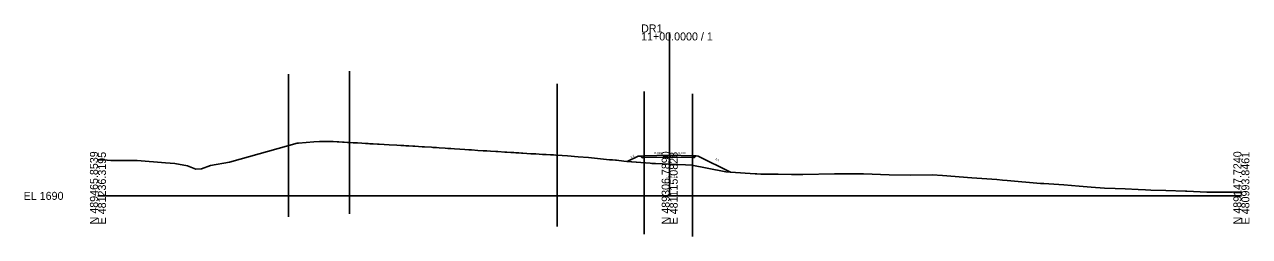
# Model space of a CAD drawing. Extents: x -26 to 403, y -28 to 1060.
# Drawn here: x -25.7 to 402.8, y 985.7 to 1060.1 of the extents above; entities that cross this region are included whole.
import ezdxf

# ---------------------------------------------------------------- set-up
doc = ezdxf.new("R2010")
doc.units = 0
for name, color, linetype in [('Exist Cross Section Cell', 7, 'Continuous'), ('Exist XS Center Line Elevation Label', 7, 'Continuous'), ('Exist XS Ground Line', 7, 'Continuous'), ('Prop XS Dump Level', 7, 'Continuous'), ('Prop XS Earthwork Shape', 7, 'Continuous'), ('Prop XS EOT Tick Mark', 7, 'Continuous'), ('Prop XS Finish Grade', 7, 'Continuous'), ('Prop XS Finish Grade Earthwork', 7, 'Continuous'), ('Prop XS Finish Grade Pavement', 7, 'Continuous'), ('Prop XS Pvmt Edge Slope', 7, 'Continuous'), ('Prop XS SE Text', 7, 'Continuous'), ('Prop XS Shoulder Borrow Shape', 7, 'Continuous'), ('Prop XS Side Slope Text', 7, 'Continuous'), ('Prop XS Subgrade Earthwork', 7, 'Continuous'), ('Scratch_Level_4', 7, 'Continuous'), ('Scratch_Level_5', 7, 'Continuous')]:
    doc.layers.add(name, color=color, linetype=linetype)

msp = doc.modelspace()

# ---------------------------------------------------------------- linework, layer by layer
at = {"layer": 'Exist Cross Section Cell'}
for p, q in [((200, 1000), (200, 1057.27)), ((0, 1000), (200, 1000)), ((200, 1000), (400, 1000))]:
    msp.add_line(p, q, dxfattribs=at)
at = {"layer": 'Exist XS Ground Line'}
msp.add_lwpolyline([(0, 1012.58), (1.9, 1012.57), (4.51, 1012.41), (13.68, 1012.41), (23.65, 1011.61), (26.89, 1011.39), (31.29, 1010.48), (34.2, 1009.4), (36.24, 1009.52), (39.35, 1010.61), (45.99, 1011.81), (69.73, 1018.47), (70.11, 1018.5), (75.53, 1018.99), (77.5, 1019.02), (77.95, 1019.04), (80.71, 1019.08), (81.19, 1019.09), (82.26, 1019.03), (83.66, 1018.95), (84.25, 1018.91), (85.54, 1018.85), (86.14, 1018.81), (87.35, 1018.74), (88.27, 1018.69), (89.29, 1018.63), (89.8, 1018.6), (90.81, 1018.54), (92.36, 1018.45), (93.61, 1018.38), (94.49, 1018.32), (95.17, 1018.29), (96.29, 1018.22), (97.75, 1018.14), (98.32, 1018.11), (100.1, 1018.01), (101.9, 1017.91), (104.6, 1017.75), (106.01, 1017.66), (106.98, 1017.61), (107.73, 1017.56), (108.76, 1017.5), (110.1, 1017.42), (110.55, 1017.39), (110.89, 1017.37), (113.4, 1017.22), (114.2, 1017.17), (116.65, 1017.02), (117.16, 1016.99), (117.69, 1016.96), (118.39, 1016.92), (119.31, 1016.87), (121.41, 1016.72), (122.43, 1016.65), (123.03, 1016.61), (123.46, 1016.58), (124.78, 1016.49), (126.61, 1016.37), (128.36, 1016.25), (129.75, 1016.15), (130.16, 1016.13), (130.71, 1016.09), (132.88, 1015.95), (134.77, 1015.83), (135.49, 1015.79), (136.04, 1015.75), (137.29, 1015.67), (139.17, 1015.55), (139.86, 1015.5), (142.33, 1015.34), (143.02, 1015.3), (144.43, 1015.21), (145.47, 1015.15), (146.22, 1015.1), (147.2, 1015.04), (148.15, 1014.98), (148.61, 1014.95), (151.43, 1014.78), (152.15, 1014.74), (153.19, 1014.68), (154.37, 1014.61), (155.53, 1014.54), (156.75, 1014.47), (158.33, 1014.39), (159.33, 1014.33), (160.17, 1014.28), (162.37, 1014.17), (164.25, 1014.01), (167.95, 1013.72), (171.56, 1013.43), (178.9, 1012.67), (180.02, 1012.57), (181.06, 1012.49), (181.4, 1012.46), (183.96, 1012.12), (185.01, 1012.01), (193.23, 1011.44), (193.78, 1011.39), (194.08, 1011.39), (194.72, 1011.36), (195.02, 1011.35), (200, 1011.11), (205.57, 1010.85), (207.76, 1010.79), (213.14, 1009.67), (219.65, 1008.43), (221.26, 1008.28), (229.86, 1007.77), (230.49, 1007.71), (231.92, 1007.65), (237.99, 1007.59), (242.62, 1007.44), (246.64, 1007.43), (257.7, 1007.68), (264.92, 1007.73), (266.54, 1007.76), (267.77, 1007.76), (276.75, 1007.37), (284.2, 1007.28), (291.78, 1007.35), (295.41, 1007.13), (305.75, 1006.29), (314.42, 1005.71), (316.49, 1005.54), (318.07, 1005.43), (329.78, 1004.38), (330.92, 1004.28), (337.9, 1003.82), (343.22, 1003.38), (347.42, 1003.02), (352.17, 1002.65), (355.8, 1002.53), (359.31, 1002.45), (363.92, 1002.21), (366.45, 1002.07), (368.37, 1002.01), (373.58, 1001.89), (380.42, 1001.67), (380.95, 1001.64), (387.86, 1001.34), (393.53, 1001.31), (394.99, 1001.33), (396.92, 1001.35), (400, 1001.38)], dxfattribs=at)
at = {"layer": 'Prop XS Dump Level'}
for p, q in [((191.12, 1014.06), (200, 1014.23)), ((200, 1014.23), (208, 1014.07))]:
    msp.add_line(p, q, dxfattribs=at)
at = {"layer": 'Prop XS Earthwork Shape'}
msp.add_lwpolyline([(189.74, 1013.96), (188.93, 1013.9), (185.15, 1012), (193.23, 1011.44), (193.78, 1011.39), (194.08, 1011.39), (194.72, 1011.36), (195.02, 1011.35), (200, 1011.11), (205.57, 1010.85), (207.76, 1010.79), (213.14, 1009.67), (219.65, 1008.43), (221.26, 1008.28), (210, 1013.91), (209.26, 1013.97), (208.68, 1013.39), (208, 1013.41), (200, 1013.57), (191.12, 1013.39), (190.38, 1013.38)], close=True, dxfattribs=at)
at = {"layer": 'Prop XS EOT Tick Mark'}
for p, q in [((191.12, 1014.06), (191.12, 1015.06)), ((208, 1014.07), (208, 1015.07))]:
    msp.add_line(p, q, dxfattribs=at)
at = {"layer": 'Prop XS Finish Grade'}
for p, q in [((191.12, 1014.06), (189.74, 1013.96)), ((208, 1014.07), (209.26, 1013.97))]:
    msp.add_line(p, q, dxfattribs=at)
at = {"layer": 'Prop XS Finish Grade Earthwork'}
for p, q in [((188.93, 1013.9), (185.15, 1012)), ((189.74, 1013.96), (188.93, 1013.9)), ((209.26, 1013.97), (210, 1013.91)), ((210, 1013.91), (221.26, 1008.28))]:
    msp.add_line(p, q, dxfattribs=at)
at = {"layer": 'Prop XS Finish Grade Pavement'}
for p, q in [((191.12, 1014.06), (200, 1014.23)), ((200, 1014.23), (208, 1014.07))]:
    msp.add_line(p, q, dxfattribs=at)
at = {"layer": 'Prop XS Pvmt Edge Slope'}
for p, q in [((191.12, 1014.06), (190.38, 1013.38)), ((208, 1014.07), (208.68, 1013.39))]:
    msp.add_line(p, q, dxfattribs=at)
at = {"layer": 'Prop XS Shoulder Borrow Shape'}
for points in [[(191.12, 1014.06), (190.38, 1013.38), (189.74, 1013.96)], [(208.68, 1013.39), (209.26, 1013.97), (208, 1014.07)]]:
    msp.add_lwpolyline(points, close=True, dxfattribs=at)
at = {"layer": 'Prop XS Subgrade Earthwork'}
for p, q in [((190.38, 1013.38), (189.74, 1013.96)), ((191.12, 1013.39), (190.38, 1013.38)), ((200, 1013.57), (191.12, 1013.39)), ((208, 1013.41), (200, 1013.57)), ((208, 1013.41), (208.68, 1013.39)), ((208.68, 1013.39), (209.26, 1013.97))]:
    msp.add_line(p, q, dxfattribs=at)
at = {"layer": 'Scratch_Level_4'}
for p, q in [((66.64, 1042.6), (66.64, 992.6)), ((87.99, 1043.7), (87.99, 993.7)), ((160.61, 1039.26), (160.61, 989.26)), ((191.12, 1036.59), (191.12, 986.59)), ((208, 1035.74), (208, 985.74))]:
    msp.add_line(p, q, dxfattribs=at)
at = {"layer": 'Scratch_Level_5'}
msp.add_lwpolyline([(0, 1012.58), (1.9, 1012.57), (4.51, 1012.41), (13.68, 1012.41), (23.65, 1011.61), (26.89, 1011.39), (31.29, 1010.48), (34.2, 1009.4), (36.24, 1009.52), (39.35, 1010.61), (45.99, 1011.81), (69.73, 1018.47), (70.11, 1018.5), (75.53, 1018.99), (77.5, 1019.02), (77.95, 1019.04), (80.71, 1019.08), (81.19, 1019.09), (82.26, 1019.03), (83.66, 1018.95), (84.25, 1018.91), (85.54, 1018.85), (86.14, 1018.81), (87.35, 1018.74), (88.27, 1018.69), (89.29, 1018.63), (89.8, 1018.6), (90.81, 1018.54), (92.36, 1018.45), (93.61, 1018.38), (94.49, 1018.32), (95.17, 1018.29), (96.29, 1018.22), (97.75, 1018.14), (98.32, 1018.11), (100.1, 1018.01), (101.9, 1017.91), (104.6, 1017.75), (106.01, 1017.66), (106.98, 1017.61), (107.73, 1017.56), (108.76, 1017.5), (110.1, 1017.42), (110.55, 1017.39), (110.89, 1017.37), (113.4, 1017.22), (114.2, 1017.17), (116.65, 1017.02), (117.16, 1016.99), (117.69, 1016.96), (118.39, 1016.92), (119.31, 1016.87), (121.41, 1016.72), (122.43, 1016.65), (123.03, 1016.61), (123.46, 1016.58), (124.78, 1016.49), (126.61, 1016.37), (128.36, 1016.25), (129.75, 1016.15), (130.16, 1016.13), (130.71, 1016.09), (132.88, 1015.95), (134.77, 1015.83), (135.49, 1015.79), (136.04, 1015.75), (137.29, 1015.67), (139.17, 1015.55), (139.86, 1015.5), (142.33, 1015.34), (143.02, 1015.3), (144.43, 1015.21), (145.47, 1015.15), (146.22, 1015.1), (147.2, 1015.04), (148.15, 1014.98), (148.61, 1014.95), (151.43, 1014.78), (152.15, 1014.74), (153.19, 1014.68), (154.37, 1014.61), (155.53, 1014.54), (156.75, 1014.47), (158.33, 1014.39), (159.33, 1014.33), (160.17, 1014.28), (162.37, 1014.17), (164.25, 1014.01), (167.95, 1013.72), (171.56, 1013.43), (178.9, 1012.67), (180.02, 1012.57), (181.06, 1012.49), (181.4, 1012.46), (183.96, 1012.12), (185.01, 1012.01), (193.23, 1011.44), (193.78, 1011.39), (194.08, 1011.39), (194.72, 1011.36), (195.02, 1011.35), (200, 1011.11), (205.57, 1010.85), (207.76, 1010.79), (213.14, 1009.67), (219.65, 1008.43), (221.26, 1008.28), (229.86, 1007.77), (230.49, 1007.71), (231.92, 1007.65), (237.99, 1007.59), (242.62, 1007.44), (246.64, 1007.43), (257.7, 1007.68), (264.92, 1007.73), (266.54, 1007.76), (267.77, 1007.76), (276.75, 1007.37), (284.2, 1007.28), (291.78, 1007.35), (295.41, 1007.13), (305.75, 1006.29), (314.42, 1005.71), (316.49, 1005.54), (318.07, 1005.43), (329.78, 1004.38), (330.92, 1004.28), (337.9, 1003.82), (343.22, 1003.38), (347.42, 1003.02), (352.17, 1002.65), (355.8, 1002.53), (359.31, 1002.45), (363.92, 1002.21), (366.45, 1002.07), (368.37, 1002.01), (373.58, 1001.89), (380.42, 1001.67), (380.95, 1001.64), (387.86, 1001.34), (393.53, 1001.31), (394.99, 1001.33), (396.92, 1001.35), (400, 1001.38)], dxfattribs=at)

# ---------------------------------------------------------------- texts
at = {"layer": 'Exist Cross Section Cell'}
for s, p in [('DR1', (190, 1057.27)), ('11+00.0000 / 1', (190, 1054.47)), ('EL 1690', (-26, 998.6))]:
    msp.add_text(s, height=2.8, dxfattribs=at).set_placement(p)
for s, p in [('N 489465.8539', (0, 990)), ('E 481236.3195', (2.8, 990)), ('N 489306.7890', (200, 990)), ('E 481115.0828', (202.8, 990)), ('N 489147.7240', (400, 990)), ('E 480993.8461', (402.8, 990))]:
    msp.add_text(s, height=2.8, rotation=90, dxfattribs=at).set_placement(p)
at = {"layer": 'Exist XS Center Line Elevation Label'}
msp.add_text('1701.11', height=0.75, dxfattribs=at).set_placement((198.76, 1006.36))
at = {"layer": 'Prop XS Dump Level'}
for p in [(188.93, 1013.86), (210, 1013.87)]:
    msp.add_text('Case1', height=0.04, dxfattribs=at).set_placement(p)
at = {"layer": 'Prop XS SE Text'}
for rotation, p in [(1.1458, (194.69, 1014.62)), (358.8542, (203.09, 1014.68))]:
    msp.add_text('0.020', height=0.75, rotation=rotation, dxfattribs=at).set_placement(p)
at = {"layer": 'Prop XS Side Slope Text'}
for rotation, p in [(26.5651, (186.51, 1013.18)), (333.4349, (215.87, 1012.66))]:
    msp.add_text('2:1', height=0.75, rotation=rotation, dxfattribs=at).set_placement(p)

doc.saveas('drawing.dxf')
